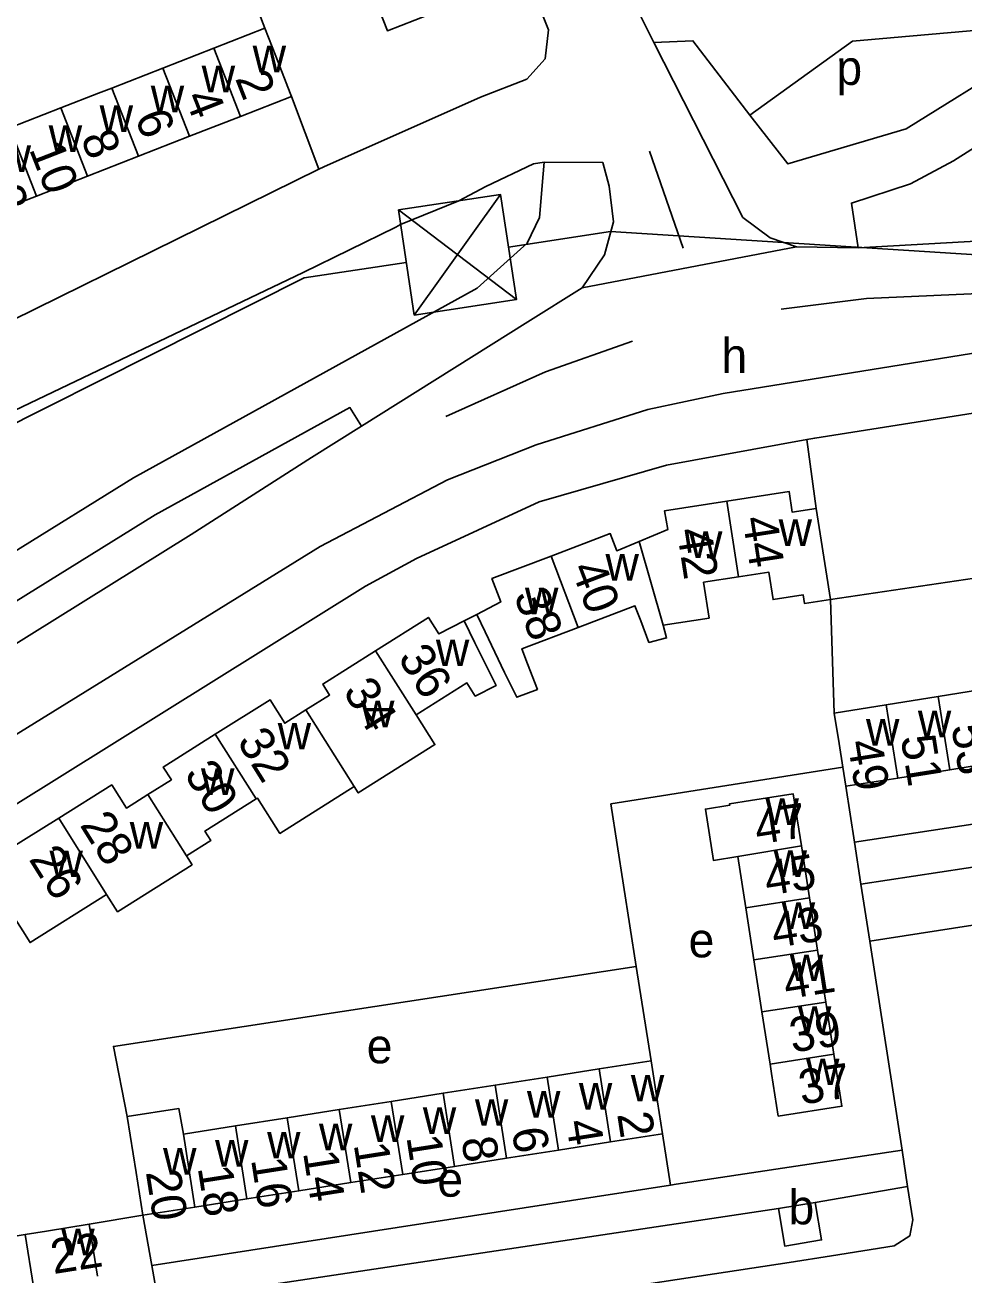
# Model space of a CAD drawing. Extents: x 159675 to 162108, y 386471 to 388472.
# Drawn here: x 160245.5 to 160354.1, y 387363.3 to 387507.9 of the extents above; entities that cross this region are included whole.
import ezdxf

# ---------------------------------------------------------------- set-up
doc = ezdxf.new("R2010")
doc.units = 0
for name, color, linetype in [('BLT_Basislijn', 7, 'Continuous'), ('BLT_Bebouwing', 7, 'Continuous'), ('BLT_Centroide', 7, 'Continuous'), ('BLT_Hoogspanningsmast_en_leidingen', 7, 'Continuous'), ('BLT_Huisnummer', 7, 'Continuous'), ('BLT_Huisnummer_ tussenligend', 7, 'Continuous'), ('BLT_Onderverdeling_panden', 7, 'Continuous'), ('BLT_Vlakafsluiter', 7, 'Continuous')]:
    doc.layers.add(name, color=color, linetype=linetype)

msp = doc.modelspace()

# ---------------------------------------------------------------- linework, layer by layer
at = {"layer": 'BLT_Basislijn'}
for p, q in [((160269.2, 387517.97), (160273.21, 387507.52)), ((160279.46, 387491.22), (160276.29, 387499.63)), ((160317.67, 387493.29), (160321.58, 387482.07)), ((160295.64, 387487.57), (160288.9, 387484.8)), ((160288.36, 387484.51), (160277.64, 387479.27)), ((160288.36, 387484.51), (160288.9, 387484.8)), ((160336.97, 387451.96), (160335.88, 387459.94)), ((160338.6, 387441.42), (160397.29, 387450.18)), ((160338.6, 387441.42), (160339.05, 387428.3)), ((160296.24, 387438.95), (160297.71, 387439.71)), ((160341.39, 387413.36), (160424.99, 387426.05)), ((160342.14, 387408.5), (160425.71, 387421.15)), ((160340.39, 387419.83), (160341.39, 387413.36)), ((160341.39, 387413.36), (160342.14, 387408.5)), ((160342.14, 387408.5), (160343.16, 387401.92)), ((160343.16, 387401.92), (160346.9, 387377.71)), ((160317.87, 387388.06), (160316.16, 387398.99)), ((160320.1, 387373.66), (160319.19, 387379.61)), ((160346.9, 387377.71), (160347.54, 387373.53)), ((160260.13, 387364.39), (160320.1, 387373.66)), ((160336.86, 387371.67), (160347.54, 387373.53)), ((160252.9, 387369.15), (160259.1, 387370.2)), ((160259.1, 387370.2), (160260.13, 387364.39)), ((160260.88, 387360.22), (160332.6, 387370.97)), ((160260.13, 387364.39), (160260.88, 387360.22))]:
    msp.add_line(p, q, dxfattribs=at)
for points in [[(160279.46, 387491.22), (160280.02, 387491.49), (160298.16, 387499.55), (160303.51, 387501.62), (160305.61, 387504), (160306.01, 387507.33), (160287.01, 387554.89), (160285.5, 387556.48), (160284.21, 387556.61), (160258.21, 387546.8)], [(160318.2, 387505.88), (160316.12, 387510.05), (160316, 387510.37)], [(160329.29, 387497.46), (160341.15, 387506.04), (160359.18, 387507.61)], [(160318.2, 387505.88), (160322.71, 387506.07), (160329.29, 387497.46)], [(160334.68, 387482.24), (160331.63, 387483.27), (160328.47, 387485.63), (160318.2, 387505.88)], [(160329.29, 387497.46), (160333.67, 387491.82), (160347.36, 387495.89), (160360.26, 387503.91)], [(160341.81, 387482.13), (160389.5, 387484.83), (160417.13, 387490), (160494.83, 387503.45)], [(160341.81, 387482.13), (160341.04, 387487.29), (160347.87, 387489.54), (160352.85, 387492.2), (160364.46, 387499.55), (160364.38, 387502.1)], [(160496.09, 387494.86), (160474.62, 387491.43), (160393.7, 387476.15), (160326.19, 387465.26), (160317.49, 387463.41), (160304.59, 387459.33), (160294.34, 387455.29), (160279.59, 387447.55), (160133.6, 387357.24), (160095.66, 387329.37)], [(160305.5, 387492.01), (160305.38, 387490.68), (160304.98, 387485.64), (160303.55, 387482.65), (160297.75, 387477.45), (160258.01, 387455.52), (160160.59, 387395.03), (160158.55, 387395.01), (160157.31, 387396.38), (160148.1, 387417.01)], [(160305.5, 387492.01), (160304.29, 387491.84), (160298.78, 387489.2), (160295.64, 387487.57)], [(160305.5, 387492.01), (160312.28, 387491.99), (160313.03, 387489.27), (160313.52, 387485.11), (160312.48, 387481.29), (160309.9, 387477.48)], [(160279.46, 387491.22), (160227.51, 387465.62), (160226.76, 387465.26)], [(160341.81, 387482.13), (160334.68, 387482.24)], [(160277.64, 387479.27), (160164.41, 387425.13), (160148.1, 387417.01)], [(160309.9, 387477.48), (160303.61, 387473.55), (160284.39, 387461.48)], [(160358.35, 387476.96), (160342.78, 387476.25), (160332.93, 387475.03)], [(160335.88, 387459.94), (160336.8, 387460.1), (160417.65, 387472.85), (160418.29, 387472.64), (160420.67, 387455.64)], [(160294.14, 387462.6), (160305.67, 387467.78), (160315.73, 387471.33)], [(160284.39, 387461.48), (160283.05, 387463.63), (160260.54, 387451.21), (160149.61, 387382.32)], [(160284.39, 387461.48), (160278.61, 387457.86), (160264.71, 387448.94), (160130.55, 387365.32), (160095.03, 387345.03)], [(160130.23, 387345.94), (160140.35, 387353.06), (160173.83, 387373.66), (160284.85, 387442.96), (160290.74, 387446.18), (160304.94, 387452.72), (160319.66, 387456.96), (160335.88, 387459.94)], [(160316.16, 387398.99), (160313.23, 387417.78), (160340.04, 387422.05)], [(160343.16, 387401.92), (160423.78, 387414.45), (160425.36, 387415.46), (160426.02, 387416.43), (160426.22, 387417.66), (160425.71, 387421.15)], [(160257.31, 387381.61), (160255.71, 387389.73), (160316.16, 387398.99)], [(160320.1, 387373.66), (160320.78, 387373.77), (160346.9, 387377.71)], [(160262.01, 387353.82), (160333.85, 387364.71), (160338.73, 387365.49), (160345.99, 387366.65), (160347.78, 387367.8), (160348.13, 387369.68), (160347.54, 387373.53)], [(160234.3, 387348.74), (160231.28, 387365.56), (160245.49, 387367.97)]]:
    msp.add_lwpolyline(points, dxfattribs=at)
at = {"layer": 'BLT_Bebouwing'}
for p, q in [((160267.32, 387505.21), (160273.21, 387507.52)), ((160261.42, 387502.91), (160267.32, 387505.21)), ((160255.52, 387500.6), (160261.42, 387502.91)), ((160276.29, 387499.63), (160270.4, 387497.33)), ((160249.62, 387498.3), (160243.73, 387495.99)), ((160270.4, 387497.33), (160264.5, 387495.03)), ((160264.5, 387495.03), (160258.6, 387492.72)), ((160258.6, 387492.72), (160252.7, 387490.42)), ((160252.7, 387490.42), (160246.81, 387488.11)), ((160246.81, 387488.11), (160240.91, 387485.81)), ((160357.06, 387431.16), (160351.05, 387430.21)), ((160351.05, 387430.21), (160345.05, 387429.25)), ((160345.05, 387429.25), (160339.05, 387428.3)), ((160352.4, 387421.74), (160358.4, 387422.69)), ((160340.04, 387422.05), (160340.39, 387419.83)), ((160340.39, 387419.83), (160346.4, 387420.78)), ((160346.4, 387420.78), (160352.4, 387421.74)), ((160336.19, 387406.9), (160335.25, 387412.92)), ((160328.82, 387405.75), (160327.9, 387411.68)), ((160337.12, 387400.88), (160336.19, 387406.9)), ((160329.76, 387399.73), (160328.82, 387405.75)), ((160338.06, 387394.86), (160337.12, 387400.88)), ((160330.69, 387393.71), (160329.76, 387399.73)), ((160339, 387388.84), (160338.06, 387394.86)), ((160331.63, 387387.69), (160330.69, 387393.71)), ((160317.87, 387388.06), (160311.86, 387387.12)), ((160305.85, 387386.18), (160299.84, 387385.24)), ((160311.86, 387387.12), (160305.85, 387386.18)), ((160299.84, 387385.24), (160293.83, 387384.3)), ((160287.82, 387383.36), (160281.81, 387382.41)), ((160293.83, 387384.3), (160287.82, 387383.36)), ((160281.81, 387382.41), (160275.81, 387381.47)), ((160269.8, 387380.53), (160263.79, 387379.59)), ((160275.81, 387381.47), (160269.8, 387380.53)), ((160313.18, 387378.67), (160319.19, 387379.61)), ((160301.17, 387376.79), (160307.17, 387377.73)), ((160307.17, 387377.73), (160313.18, 387378.67)), ((160295.16, 387375.85), (160301.17, 387376.79)), ((160283.14, 387373.97), (160289.15, 387374.91)), ((160289.15, 387374.91), (160295.16, 387375.85)), ((160277.13, 387373.03), (160283.14, 387373.97)), ((160265.11, 387371.14), (160271.12, 387372.09)), ((160271.12, 387372.09), (160277.13, 387373.03)), ((160332.6, 387370.97), (160336.86, 387371.67)), ((160259.1, 387370.2), (160265.11, 387371.14)), ((160253.86, 387363.14), (160252.9, 387369.15)), ((160246.45, 387361.96), (160245.49, 387367.97))]:
    msp.add_line(p, q, dxfattribs=at)
for points in [[(160292.95, 387516.32), (160295.29, 387510.32), (160287.39, 387507.24), (160285.05, 387513.24)], [(160273.21, 387507.52), (160274.47, 387504.29), (160276.15, 387500), (160276.29, 387499.63)], [(160255.52, 387500.6), (160253.97, 387500), (160249.62, 387498.3)], [(160326.63, 387452.81), (160319.44, 387451.7), (160319.81, 387449.54), (160316.5, 387448.16)], [(160336.97, 387451.96), (160334.2, 387451.53), (160333.83, 387453.93), (160326.63, 387452.81)], [(160338.6, 387441.42), (160337.42, 387449.04), (160336.97, 387451.96)], [(160316.5, 387448.16), (160313.9, 387447.08), (160313.15, 387449.05), (160306.31, 387446.45)], [(160306.31, 387446.45), (160299.47, 387443.85), (160300.49, 387441.15), (160297.71, 387439.71)], [(160327.99, 387444.05), (160323.94, 387443.43), (160324.58, 387439.29), (160319.28, 387438.47)], [(160338.6, 387441.42), (160335.62, 387440.96), (160335.46, 387441.96), (160331.98, 387441.43), (160331.49, 387444.59), (160327.99, 387444.05)], [(160297.71, 387439.71), (160298.67, 387437.7), (160300.93, 387432.98), (160302.35, 387430.12), (160304.72, 387431.02), (160303.59, 387433.99), (160302.93, 387435.73), (160309.44, 387438.2)], [(160319.28, 387438.47), (160319.66, 387436.99), (160317.62, 387436.46), (160316.68, 387438.95), (160316.01, 387440.7), (160309.44, 387438.2)], [(160296.24, 387438.95), (160293.34, 387437.45), (160292.13, 387439.36), (160286.02, 387435.5)], [(160296.24, 387438.95), (160297.51, 387436.42), (160299.96, 387431.5), (160297.55, 387430.25), (160296.58, 387431.79), (160290.7, 387428.08)], [(160286.02, 387435.5), (160279.9, 387431.64), (160280.7, 387430.38), (160277.97, 387428.66)], [(160277.97, 387428.66), (160275.52, 387427.11), (160273.81, 387429.83), (160267.48, 387425.84)], [(160290.7, 387428.08), (160292.87, 387424.65), (160284.01, 387419.06), (160283.55, 387419.79)], [(160339.05, 387428.3), (160339.61, 387424.77), (160340.04, 387422.05)], [(160267.48, 387425.84), (160261.47, 387422.05), (160262.4, 387420.58), (160259.7, 387418.87)], [(160259.7, 387418.87), (160257.2, 387417.3), (160255.51, 387419.98), (160249.39, 387416.14)], [(160283.55, 387419.79), (160274.95, 387414.36), (160272.36, 387418.46), (160272.2, 387418.36)], [(160272.2, 387418.36), (160266.29, 387414.63), (160266.97, 387413.55), (160264.15, 387411.77)], [(160327.9, 387411.68), (160325.08, 387411.24), (160324.15, 387417.19), (160326.97, 387417.63), (160326.94, 387417.8), (160329.37, 387418.17), (160334.31, 387418.94), (160335.25, 387412.92)], [(160242.52, 387407.36), (160242.08, 387408.05), (160241.71, 387408.65), (160244.47, 387410.39), (160243.26, 387412.3), (160249.39, 387416.14)], [(160264.15, 387411.77), (160264.8, 387410.75), (160256.18, 387405.3), (160254.92, 387407.32)], [(160254.92, 387407.32), (160246.07, 387401.73), (160245.21, 387403.11), (160243.37, 387406.01), (160242.52, 387407.36)], [(160319.19, 387379.61), (160318.41, 387384.55), (160317.87, 387388.06)], [(160339, 387388.84), (160339.93, 387382.81), (160332.57, 387381.66), (160331.8, 387386.61), (160331.63, 387387.69)], [(160263.79, 387379.59), (160263.28, 387382.54), (160257.31, 387381.61)], [(160257.31, 387381.61), (160258.33, 387375.14), (160259.1, 387370.2)], [(160336.86, 387371.67), (160337.58, 387367.33), (160333.32, 387366.62), (160332.6, 387370.97)], [(160245.49, 387367.97), (160247.97, 387368.36), (160252.9, 387369.15)]]:
    msp.add_lwpolyline(points, dxfattribs=at)
at = {"layer": 'BLT_Hoogspanningsmast_en_leidingen'}
for p, q in [((160300.45, 387488.3), (160290.49, 387474.33)), ((160288.65, 387486.51), (160302.3, 387476.13)), ((160301.37, 387482.21), (160313.17, 387484.01)), ((160313.17, 387484.01), (160510.13, 387471.41)), ((160277.77, 387478.63), (160289.57, 387480.42)), ((160104.84, 387391.65), (160277.77, 387478.63))]:
    msp.add_line(p, q, dxfattribs=at)
msp.add_lwpolyline([(160288.65, 387486.51), (160290.49, 387474.33), (160302.3, 387476.13), (160300.45, 387488.3)], close=True, dxfattribs=at)
at = {"layer": 'BLT_Onderverdeling_panden'}
for p, q in [((160270.4, 387497.33), (160267.32, 387505.21)), ((160264.5, 387495.03), (160261.42, 387502.91)), ((160258.6, 387492.72), (160255.52, 387500.6)), ((160252.7, 387490.42), (160249.62, 387498.3)), ((160246.81, 387488.11), (160243.73, 387495.99)), ((160326.63, 387452.81), (160327.99, 387444.05)), ((160316.5, 387448.16), (160319.28, 387438.47)), ((160306.31, 387446.45), (160309.44, 387438.2)), ((160286.02, 387435.5), (160290.7, 387428.08)), ((160352.4, 387421.74), (160351.05, 387430.21)), ((160277.97, 387428.66), (160283.55, 387419.79)), ((160346.4, 387420.78), (160345.05, 387429.25)), ((160272.2, 387418.36), (160267.48, 387425.84)), ((160249.39, 387416.14), (160254.92, 387407.32)), ((160327.9, 387411.68), (160335.25, 387412.92)), ((160328.82, 387405.75), (160336.19, 387406.9)), ((160329.76, 387399.73), (160337.12, 387400.88)), ((160330.69, 387393.71), (160338.06, 387394.86)), ((160331.63, 387387.69), (160339, 387388.84)), ((160307.17, 387377.73), (160305.85, 387386.18)), ((160313.18, 387378.67), (160311.86, 387387.12)), ((160301.17, 387376.79), (160299.84, 387385.24)), ((160289.15, 387374.91), (160287.82, 387383.36)), ((160295.16, 387375.85), (160293.83, 387384.3)), ((160283.14, 387373.97), (160281.81, 387382.41)), ((160271.12, 387372.09), (160269.8, 387380.53)), ((160277.13, 387373.03), (160275.81, 387381.47)), ((160265.11, 387371.14), (160263.79, 387379.59))]:
    msp.add_line(p, q, dxfattribs=at)
msp.add_lwpolyline([(160259.7, 387418.87), (160264.15, 387411.77)], dxfattribs=at)
at = {"layer": 'BLT_Vlakafsluiter'}
msp.add_line((160309.9, 387477.48), (160334.68, 387482.24), dxfattribs=at)

# ---------------------------------------------------------------- texts
at = {"layer": 'BLT_Centroide'}
for s, p in [('w', (160271.8, 387502.42)), ('p', (160339.3, 387500.97)), ('w', (160265.91, 387500.11)), ('w', (160260.02, 387497.81)), ('w', (160254.11, 387495.52)), ('w', (160248.22, 387493.2)), ('w', (160242.31, 387490.89)), ('h', (160326.01, 387467.65)), ('w', (160332.62, 387447.64)), ('w', (160322.25, 387446.23)), ('w', (160312.6, 387443.62)), ('w', (160303.29, 387439.72)), ('w', (160292.99, 387433.72)), ('w', (160284.33, 387426.64)), ('w', (160348.72, 387425.5)), ('w', (160274.7, 387424.09)), ('w', (160342.72, 387424.53)), ('w', (160265.83, 387418.81)), ('w', (160331.1, 387415.34)), ('w', (160257.59, 387412.62)), ('w', (160248.31, 387409.31)), ('w', (160332.04, 387409.34)), ('w', (160332.98, 387403.31)), ('e', (160322.21, 387400.03)), ('w', (160333.91, 387397.28)), ('w', (160334.85, 387391.28)), ('e', (160284.99, 387387.77)), ('w', (160335.79, 387385.25)), ('w', (160315.53, 387383.36)), ('w', (160309.52, 387382.42)), ('w', (160297.5, 387380.55)), ('w', (160303.52, 387381.48)), ('w', (160285.48, 387378.67)), ('w', (160291.48, 387379.61)), ('w', (160279.47, 387377.72)), ('w', (160267.45, 387375.83)), ('w', (160273.47, 387376.77)), ('w', (160261.44, 387374.89)), ('e', (160293.16, 387372.34)), ('b', (160333.76, 387369.14)), ('w', (160249.67, 387365.56))]:
    msp.add_text(s, height=4, dxfattribs=at).set_placement(p)
at = {"layer": 'BLT_Huisnummer'}
for s, rotation, p in [('2', 291.3462, (160269.74, 387501.73)), ('6', 291.3462, (160258.13, 387497.24)), ('10', 291.3438, (160245.91, 387493.55)), ('44', 278.7855, (160328.43, 387450.82)), ('38', 290.7987, (160301.96, 387441.92)), ('34', 302.025, (160282.17, 387430.8)), ('53', 279.031, (160352.59, 387426.8)), ('49', 279.031, (160340.58, 387424.94)), ('30', 302.025, (160263.81, 387421.24)), ('47', 8.8484, (160330.16, 387413.08)), ('26', 302.025, (160245.85, 387411.4)), ('41', 8.8484, (160333.5, 387395.18)), ('37', 8.8484, (160335.26, 387382.98)), ('2', 278.9022, (160313.94, 387381.9)), ('6', 278.9022, (160301.75, 387380.11)), ('10', 278.9022, (160289.57, 387379.24)), ('14', 278.9022, (160277.62, 387377.44)), ('20', 278.9022, (160259.44, 387375.2)), ('22', 9.0429, (160248.77, 387363.38))]:
    msp.add_text(s, height=4, rotation=rotation, dxfattribs=at).set_placement(p)
at = {"layer": 'BLT_Huisnummer_ tussenligend'}
for s, rotation, p in [('4', 291.3462, (160263.89, 387499.55)), ('8', 291.3438, (160251.88, 387494.85)), ('12', 291.3476, (160240.15, 387491.26)), ('42', 278.7855, (160320.83, 387449.46)), ('40', 290.7987, (160308.55, 387445.04)), ('36', 302.0297, (160288.52, 387434.68)), ('32', 302.0297, (160269.91, 387425.01)), ('51', 279.0317, (160346.73, 387425.51)), ('28', 302.0297, (160251.75, 387415.35)), ('45', 8.8467, (160331.29, 387407.16)), ('43', 8.8467, (160332.11, 387401.11)), ('39', 8.8467, (160334.19, 387389)), ('4', 278.9012, (160308.02, 387381.02)), ('8', 278.9012, (160295.92, 387379.03)), ('12', 278.9012, (160283.48, 387378.38)), ('16', 278.9012, (160271.61, 387376.64)), ('18', 278.9012, (160265.44, 387375.7))]:
    msp.add_text(s, height=4, rotation=rotation, dxfattribs=at).set_placement(p)

doc.saveas('drawing.dxf')
